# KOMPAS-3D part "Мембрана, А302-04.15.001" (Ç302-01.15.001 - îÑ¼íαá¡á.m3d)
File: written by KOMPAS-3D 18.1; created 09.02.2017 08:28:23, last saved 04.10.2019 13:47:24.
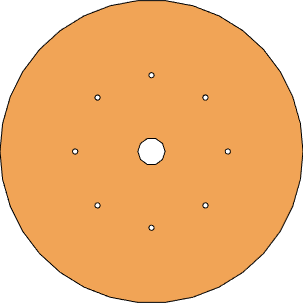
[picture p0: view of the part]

Document properties: Автор: Милов; Организация: Милов; Полное имя файла: D:\Мембранные насосы\Мембранный электропривод\А302-00.00.000 - ASTRA-302 (МЭ200)\3Д ПВХ\А302-01.15.001 - Мембрана.m3d

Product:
- Part/product: Мембрана  | designation А302-04.15.001
    Масса: 0.264223
    Раздел спецификации: Детали
    Форматы листов документа: A4
- Part/product: Мембрана  | designation А302-01.15.001
    Масса: 0.266387
    Раздел спецификации: Детали
    Форматы листов документа: A4
    source file: А302-01.15.001 - Мембрана.cdw
- Part/product: Мембрана  | designation А302-02.15.001
    Масса: 0.264223
    Раздел спецификации: Детали
    Форматы листов документа: A4

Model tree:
1. Эскиз:7
2. Операция выдавливания:12
     Расстояние 1 = 2; Расстояние 2 = 24.8832
3. Эскиз:8
4. Вырезать элемент выдавливания:1
     Расстояние 1 = 0.1
5. Зеркальный массив:1
6. Экземпляр ( 1 )
7. Экземпляр ( 2 )  (with: Вырезать элемент выдавливания:1)
8. Эскиз:9
9. Вырезать элемент выдавливания:2
     Расстояние 1 = 10
10. Массив по концентрической сетке:1  (with: Вырезать элемент выдавливания:2, Эскиз:9)  (6 pattern instances)
     Шаг 2 = 360
11. Вырезать элемент выдавливания:2  (with: Эскиз:9)  (1 pattern instances)
     N 1 = 1; Шаг 1 = 10; Шаг 2 = 360; Номер 1 = 1

Expressions: 250+28

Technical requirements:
  Gost Type A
